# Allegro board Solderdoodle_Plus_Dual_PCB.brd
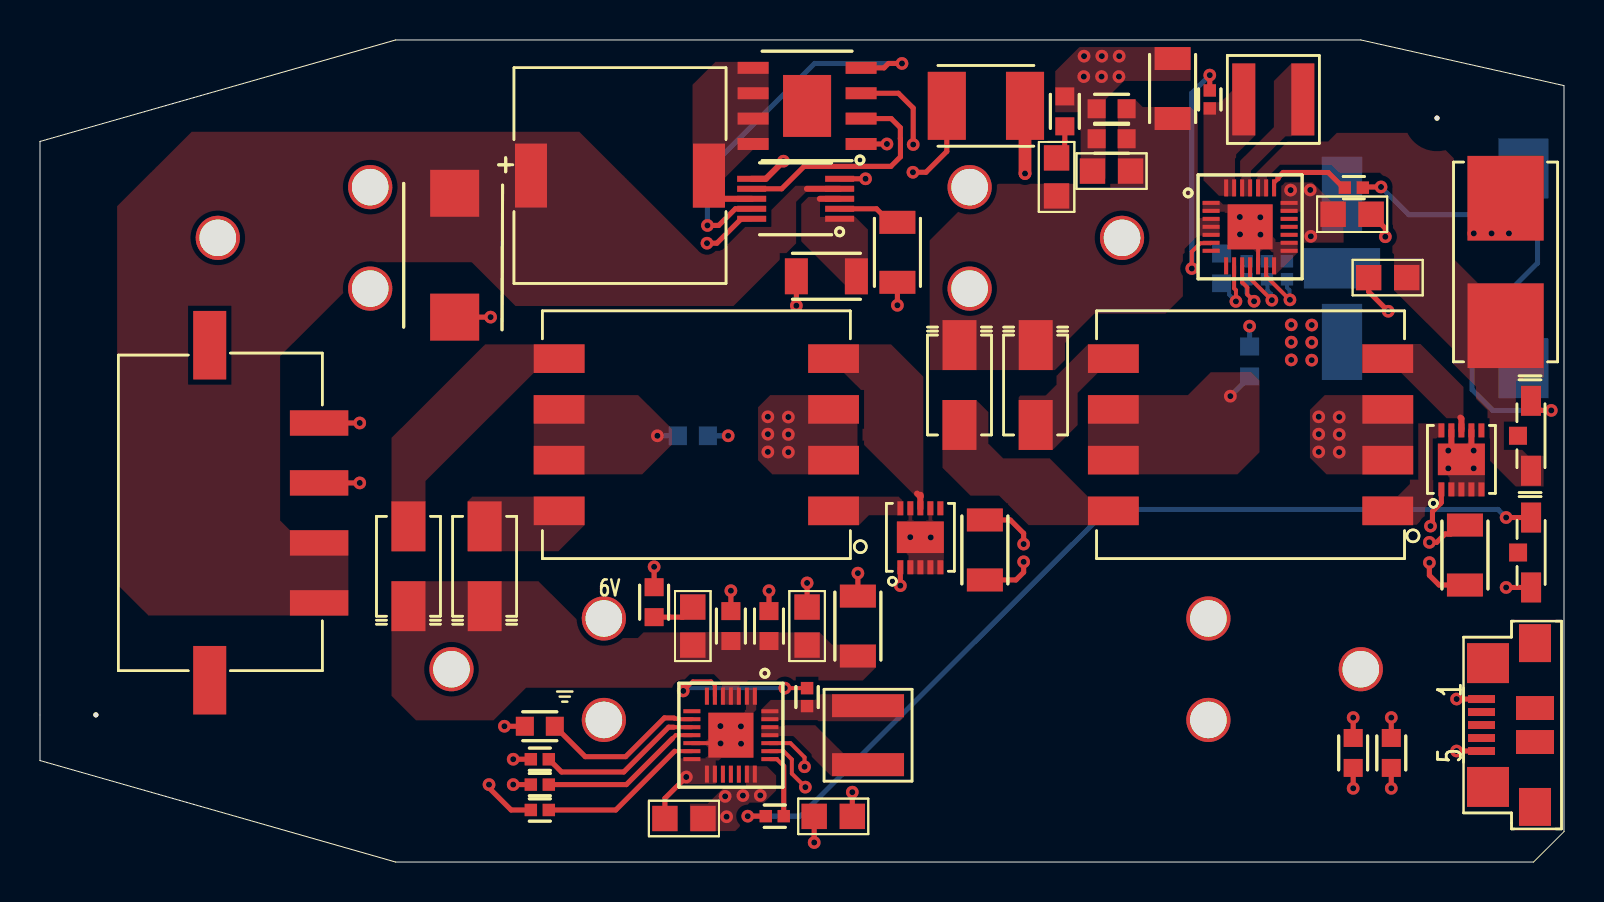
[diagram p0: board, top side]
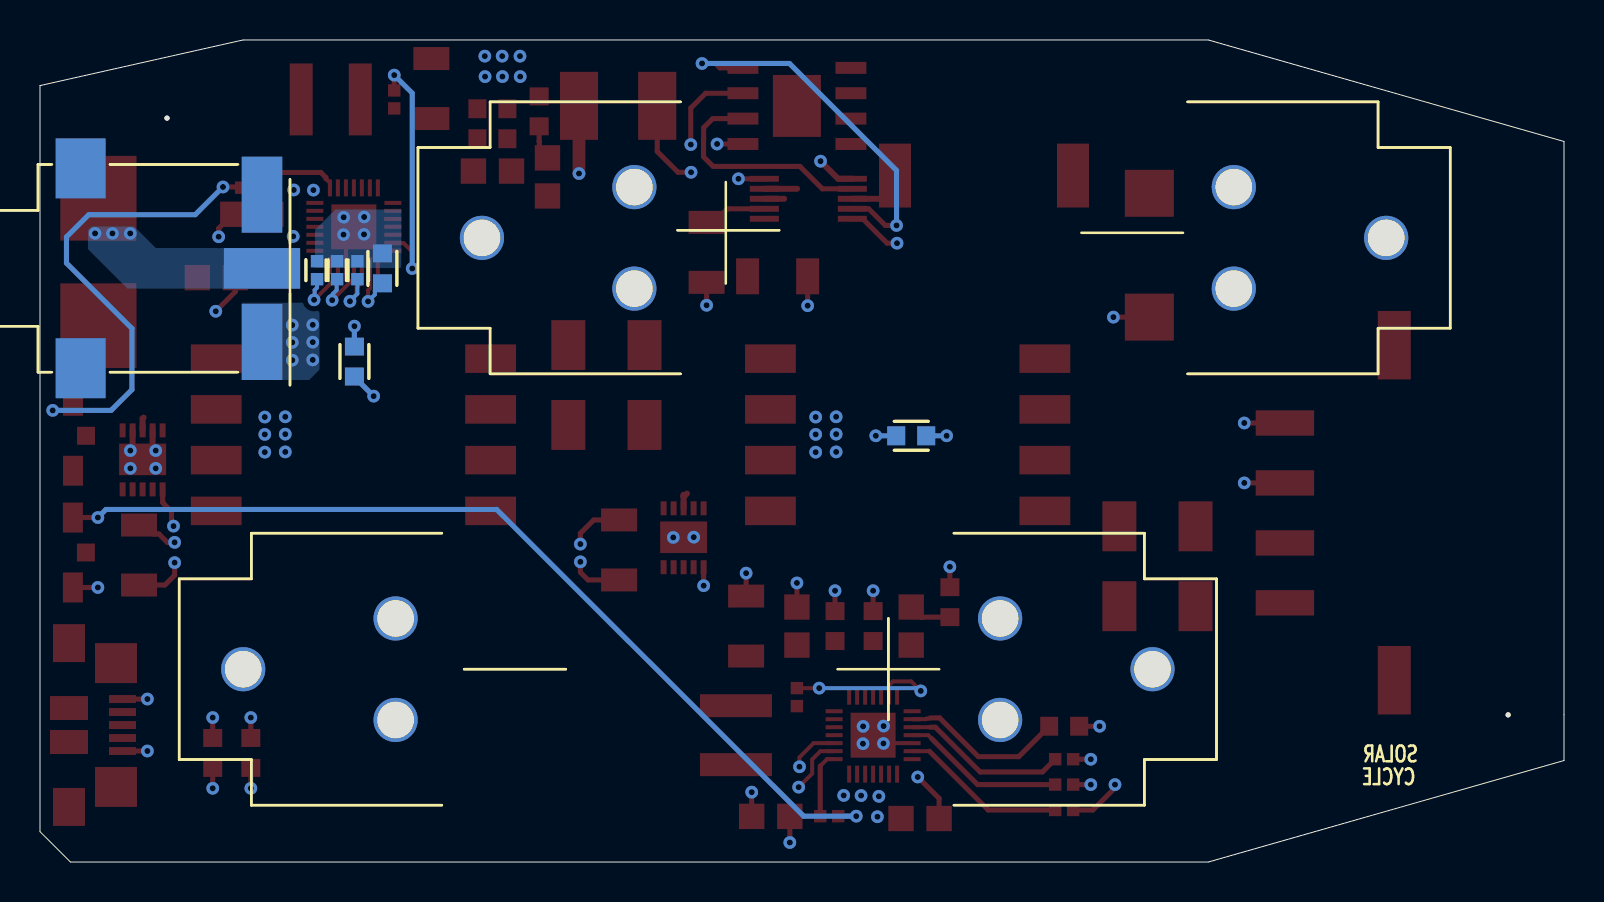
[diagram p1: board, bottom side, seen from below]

Outline 76.2 x 41.15 mm; copper layers: TOP, LAYER2_GND, LAYER3_PWR, BOTTOM. Coordinates in mm from the lower left corner of the outline.
Outline path: 0,36.07 17.78,41.15 66.04,41.15 76.2,38.86 76.2,1.52 74.68,0 17.78,0 0,5.08 0,36.07

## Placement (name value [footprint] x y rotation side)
BT1  -  [BAT_54]  46.48 31.24 0 bottom
BT2  -  [BAT_54]  28.19 9.65 180 bottom
BT3  -  [BAT_54]  16.51 31.24 180 bottom
BT4  -  [BAT_54]  58.42 9.65 0 bottom
C1  -  [C0805]  53.58 34.58 0 top
C2  -  [C0805]  38.35 11.81 270 top
C3  -  [C1206]  71.25 15.37 270 top
C4  -  [C0805]  67.38 29.25 180 top
C5  -  [C0402]  60.33 29.62 90 bottom
C6  -  [C0603]  59.08 29.72 90 bottom
C7  -  [C0402]  58.49 38.17 270 top
C8  -  [C0402]  38.35 8.25 270 top
C9  -  [C0603]  24.99 6.8 180 top
C10  -  [C0805]  50.83 34.29 270 top
C11  -  [C0805]  32.64 11.81 270 top
C12  -  [C0402]  24.99 5.15 180 top
C13  -  [C0805]  32.2 2.18 180 top
C14  -  [C0805]  39.66 2.29 0 top
C15  -  [C0603]  53.58 37.7 0 top
C16  -  [C1206]  56.63 38.72 90 top
C17  -  [C1206]  47.24 15.62 90 top
C18  -  [C0603]  34.54 11.81 270 top
C19  -  [C1206]  40.89 11.81 90 top
C20  -  [C0603]  65.66 5.46 270 top
C21  -  [C1206]  42.87 30.52 270 top
C22  -  [C1206]  39.32 29.32 180 top
C23  VAL*  [C1812]  47.29 37.85 0 top
C24  -  [C2917]  20.73 30.37 270 top
C25  -  [C0603]  67.56 5.46 270 top
C26  -  [C0805]  65.61 32.42 0 top
D1  -  [SMA]  49.78 23.88 90 top
D2  -  [SMA]  18.42 14.81 270 top
D3  -  [SMA]  45.97 23.88 90 top
D4  -  [SMA]  22.23 14.81 270 top
F1  -  [FUSE_SM]  73.28 30.04 90 top
J1  -  [4PIN_CON]  15.42 17.48 270 top
L1  -  [IND_4X4]  61.66 38.17 0 top
L2  -  [IND_4X4]  41.4 6.35 270 top
L3  -  [IND_10X10]  29 34.36 180 top
LED2  -  [LED_C110]  74.55 21.34 90 top
LED4  -  [LED_C110]  74.55 15.49 90 top
NOREF  -  []  523.95 -242.34 0 top
NOREF#2  -  []  -314.25 -255.04 0 top
NOREF#3  -  []  35.48 -64.31 0 top
NOREF#4  -  [unnamed#2]  69.85 37.24 180 bottom
NOREF#5  -  [unnamed#2]  2.79 7.37 180 bottom
R1  -  [R0603]  60.48 25.05 90 bottom
R2  -  [R0603]  53.58 36.2 0 top
R3  -  [R0402]  36.74 2.3 0 top
R4  -  [R0603]  32.64 21.34 0 bottom
R6  -  [R0603]  36.45 11.81 270 top
R7  -  [R0402]  61.35 29.62 270 bottom
R8  -  [R0402]  24.99 3.88 0 top
R10  -  [R0402]  65.69 33.75 180 top
R11  -  [R0402]  62.35 29.62 270 bottom
R12  -  [R0402]  24.99 2.61 0 top
R15  -  [R0603]  51.24 37.57 270 top
R16  -  [R0603]  30.71 13.01 270 top
S1  -  [ESWITCH]  65.1 29.72 270 bottom
T1  -  [T240V]  60.53 21.39 90 top
T2  -  [T240V]  32.82 21.39 90 top
U1  -  [SOIC_10]  71.07 20.15 90 top
U2  -  [SOIC_10]  44.02 16.26 90 top
U3  -  [QFN_28]  60.51 31.79 0 top
U4  -  [QFN_28]  34.54 6.35 270 top
U5  -  [SOP_10]  37.78 33.2 180 top
U6  -  [SOIC_8]  38.35 37.85 180 top
USB  -  [USB_B]  72.08 6.86 90 top

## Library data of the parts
BT1-BT4 = 54
C1 C2 C10 C11 C13 C26 = C0805C225K8RACTU
C3 C16 C17 C19 = GRM31CR71E106K
C4 C14 = C2012X5R1C226K
C5 C7 C8 C12 = C1005X5R1E104K
C6 C9 = C1608X5R1C225K_0P80
C15 C18 C20 C25 = GRM188R71E105K
C21 = C3216JB2E104K160AA
C22 = C3216X7R1C105M
C23 = C4532X5R1E106M
C24 = 10TPB220M
D1-D4 = B230A-13-F
F1 = 0154005_DRT
J1 = 662104145021
L1 L2 = IFSC1515AHER4R7M01
L3 = CDRH104R-7R0NC
LED2 LED4 = HSMG-C110
R1 R4 = RCS06030000Z0EA
R2 R6 = CRCW06031K00JNEAHP
R3 R10 = CRCW04022K20FKED
R7 R8 = CRCW04023K00FKED
R11 R12 = CRCW04021K20FKED
R15 R16 = ERJ-3RQJR56V
S1 = 500ASSP1SM6QE
T1 T2 = TGM-H240V8LF
U1 U2 = MAX13253ATB
U3 U4 = MAX8903GETI
U5 = MAX1791EUB
U6 = FDS8958A
USB = ZX62R-B-5P

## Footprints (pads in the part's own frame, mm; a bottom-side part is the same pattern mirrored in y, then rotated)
4PIN_CON
  rect 1.27x2.921 smd: 1(-4.501,-1.46) 2(-1.501,-1.46) 3(1.501,-1.46) 4(4.501,-1.46)
  rect 3.429x1.651 smd: 5(-8.395,-6.929) 6(8.374,-6.929)
BAT_54
  round 2.21 hole 1.829: 1(0,2.54) 2(7.62,0) 3(0,-2.54)
C0402
  rect 0.62x0.62 smd: 1(-0.45,0) 2(0.45,0)
C0603
  rect 0.899x0.95 smd: 1(-0.749,0) 2(0.749,0)
C0805
  rect 1.27x1.27 smd: 1(-0.953,0) 2(0.953,0)
C1206
  rect 1.151x1.801 smd: 1(-1.501,0) 2(1.501,0)
C1812
  rect 1.905x3.404 smd: 1(-1.956,0) 2(1.956,0)
C2917
  rect 2.349x2.451 smd: 1(-3.099,0) 2(3.099,0)
ESWITCH
  rect 3x2.499 smd: (-5.001,-9.07) (5.001,-9.07)
  rect 3.81x2.029 smd: 1(-3.686,0) 3(3.686,0)
  rect 2.029x3.81 smd: 2(0,0)
FUSE_SM
  rect 4.239x3.81 smd: 1(-3.19,0) 2(3.19,0)
IND_4X4
  rect 1.151x3.599 smd: 1(-1.476,0) 2(1.476,0)
IND_10X10
  rect 1.6x3.2 smd: 1(-4.45,0) 2(4.45,0)
LED_C110
  rect 0.899x0.899 smd: (0,0.65)
  rect 1.501x1.001 smd: 1(1.75,0) 2(-1.75,0)
QFN_28
  rect 0.851x0.201 smd: 1(-1.951,1.199) 2(-1.951,0.8) 3(-1.951,0.399) 4(-1.951,0) 5(-1.951,-0.399) 6(-1.951,-0.8) 7(-1.951,-1.199) 15(1.951,-1.199) 16(1.951,-0.8) 17(1.951,-0.399) 18(1.951,0) 19(1.951,0.399) 20(1.951,0.8) 21(1.951,1.199)
  rect 0.201x0.851 smd: 8(-1.199,-1.951) 9(-0.8,-1.951) 10(-0.399,-1.951) 11(0,-1.951) 12(0.399,-1.951) 13(0.8,-1.951) 14(1.199,-1.951) 22(1.199,1.951) 23(0.8,1.951) 24(0.399,1.951) 25(0,1.951) 26(-0.399,1.951) 27(-0.8,1.951) 28(-1.199,1.951)
  rect 2.25x2.25 smd: 29(0,0)
R0402
  rect 0.62x0.62 smd: 1(-0.45,0) 2(0.45,0)
R0603
  rect 0.899x0.95 smd: 1(-0.749,0) 2(0.749,0)
SMA
  rect 2.499x1.699 smd: 1(-1.999,0) 2(1.999,0)
SOIC_8
  rect 2.4x3.099 smd: (0,0)
  rect 1.549x0.599 smd: 1(-2.7,1.905) 2(-2.7,0.635) 3(-2.7,-0.635) 4(-2.7,-1.905) 5(2.7,-1.905) 6(2.7,-0.635) 7(2.7,0.635) 8(2.7,1.905)
SOIC_10
  rect 0.701x0.3 smd: 1(-1.501,1.001) 2(-1.501,0.5) 3(-1.501,0) 4(-1.501,-0.5) 5(-1.501,-1.001) 6(1.45,-1.001) 7(1.45,-0.5) 8(1.45,0) 9(1.45,0.5) 10(1.45,1.001)
  rect 1.58x2.349 smd: 11(0,0)
SOP_10
  rect 1.45x0.3 smd: 1(-2.2,1.001) 2(-2.2,0.5) 3(-2.2,0) 4(-2.2,-0.5) 5(-2.2,-1.001) 6(2.2,-1.001) 7(2.2,-0.5) 8(2.2,0) 9(2.2,0.5) 10(2.2,1.001)
T240V
  rect 1.43x2.54 smd: 1(-3.81,-6.861) 2(-1.27,-6.861) 3(1.27,-6.861) 4(3.81,-6.861) 5(3.81,6.861) 6(1.27,6.861) 7(-1.27,6.861) 8(-3.81,6.861)
unnamed#2
  round 0.254 hole 2.794 unplated: (0,0)
USB_B
  rect 1.9x1.6 smd: (-4.1,-2.675) (4.1,-2.675)
  rect 1.999x2.101 smd: (-3.099,-0.325) (3.099,-0.325)
  rect 1.199x1.9 smd: (-0.851,-2.675) (0.851,-2.675)
  rect 0.399x1.349 smd: 1(1.3,0) 2(0.65,0) 3(0,0) 4(-0.65,0) 5(-1.3,0)

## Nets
GND: BT3.1 BT3.2 BT3.3 C1.1 C4.2 C5.2 C6.2 C14.1 C15.1 C16.2 C26.2 LED4.2 R1.2 R2.1 R7.1 R11.1 R15.1 U3.1 U3.2 U3.12 U3.14 U3.15 U3.16 U3.29 U4.23 U4.24
BATT1: BT1.1 BT1.2 BT1.3 C26.1 U3.20 U3.21
BATT2: BT2.1 BT2.2 BT2.3 C13.1 U4.20 U4.21
F1: C4.1 F1.1 LED2.2 U3.23 U3.24
GNF: C3.2 C17.2 C20.2 C25.2 U1.2 U1.3 U1.4 U1.5 U1.7 U1.9 U1.11 U2.2 U2.3 U2.4 U2.5 U2.7 U2.9 U2.11 USB.5
GNG: BT4.1 BT4.2 BT4.3 C2.1 C9.2 C12.2 C13.2 C14.2 C18.1 C19.2 C21.2 C22.2 C23.2 C24.2 J1.2 R4.2 R6.1 R8.1 R12.1 R16.1 U4.1 U4.2 U4.12 U4.14 U4.15 U4.16 U4.29 U5.6 U6.1
LED1: LED2.1 R10.1
LED2: LED4.1 R3.1
N0006: C10.1 R15.2
N0180: D1.1 T1.5
N0181: D3.1 T1.8
N0268: R1.1 T1.6 T1.7
N0367: C11.1 R16.2
N0372: D2.1 T2.5
N0373: D4.1 T2.8
N0374: C8.2 L2.1 U4.27 U4.28
N0375: L2.2 U4.25 U4.26
N0384: R4.1 T2.6 T2.7
S1: F1.2 S1.2
U1T1: T1.1 U1.10
U1T2: T1.4 U1.8
U2T1: T2.1 U2.10
U2T2: T2.4 U2.8
U3BST: C7.1 U3.6
U3CHG: R10.2 U3.22
U3CS: L1.2 U3.25 U3.26
U3CT: C5.1 U3.10
U3DC: C1.2 C10.2 C15.2 C16.1 D1.2 D3.2 R2.2 U3.3 U3.4 U3.5
U3IDC: R7.2 U3.11
U3ISET: R11.2 U3.13
U3LX: C7.2 L1.1 U3.27 U3.28
U3VL: C6.1 U3.9
U4BST: C8.1 U4.6
U4CHG: R3.2 U4.22
U4CT: C12.1 U4.10
U4DC: C2.2 C11.2 C18.2 C19.1 D2.2 D4.2 R6.2 U4.3 U4.4 U4.5
U4IDC: R8.2 U4.11
U4ISET: R12.2 U4.13
U4VL: C9.1 U4.9
U5CS: L3.1 U5.8 U6.5 U6.6 U6.7 U6.8
U5DH: U5.9 U6.4
U5DL: U5.7 U6.2
U5OUT: C24.1 J1.3 J1.4 L3.2 U5.4
U5REF: C21.1 U5.2
U5VL: C22.1 U5.1 U5.3
U5VP: C23.1 J1.1 S1.3 U5.5 U5.10 U6.3
USB: C3.1 C17.1 C20.1 C25.1 T1.2 T1.3 T2.2 T2.3 U1.1 U2.1 USB.1

Pads without a net: J1 5 6; S1 1; U1 6; U2 6; U3 7 8 17 18 19; U4 7 8 17 18 19; USB 2 3 4

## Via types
v1: diameter 0.635, hole 0.305, TOP to BOTTOM, 107 vias

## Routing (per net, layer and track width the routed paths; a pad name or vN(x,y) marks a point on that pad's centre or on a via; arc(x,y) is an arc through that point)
GND: length 30.1
  TOP w0.198: U3.12 60.9,31.39 U3.29 ; U4.23 37.18,5.55 37.59,5.14 37.59,4.42 v1(38.27,3.75) ; U4.24 37.52,5.95 38.23,5.24 v1(38.23,4.77)
  TOP w0.254: LED4.2 v1(73.31,13.74) ; C14.1 v1(38.71,0.98) ; v1(67.27,31.3) 67.27,31.72 C26.2 ; v1(67.41,27.57) 66.43,28.55 C4.2
  LAYER2_GND w0.635: BT3.2 9.89,30.25 ; BT3.2 9.89,32.24 ; BT3.2 7.89,30.25 ; BT3.2 7.89,32.24 ; BT3.3 17.51,29.7 ; BT3.3 15.51,27.71 ; BT3.3 15.51,29.7 ; BT3.1 17.51,34.78 ; BT3.1 17.51,32.79 ; BT3.1 15.51,32.79 ; BT3.1 15.51,34.78
  BOTTOM w0.254: R1.2 v1(60.48,26.82)
  vias: v1(52.2,40.34) v1(52.19,39.31) v1(53.09,40.34) v1(53.08,39.31) v1(53.96,40.34) v1(53.95,39.31) v1(59.99,32.29) v1(60,31.42) v1(61.02,32.27) v1(61.02,31.4)
BATT1: length 16.9
  LAYER3_PWR w0.635: BT1.2 55.1,30.25 ; BT1.2 53.11,32.24 ; BT1.2 53.11,30.25 ; BT1.2 55.1,32.24 ; 45.49,29.7 BT1.1 ; BT1.1 47.48,29.7 ; BT1.1 47.48,27.71 ; BT1.1 45.49,27.71 ; 45.49,32.79 BT1.3 ; BT1.3 45.49,34.78 ; BT1.3 47.48,34.78 ; BT1.3 47.48,32.79
  vias: v1(62.53,33.63) v1(63.51,33.64) v1(63.54,31.32)
BATT2: length 16.9
  LAYER3_PWR w0.635: 27.2,11.2 BT2.1 ; BT2.1 29.19,11.2 ; BT2.1 27.2,13.19 ; BT2.1 29.19,13.19 ; BT2.3 29.19,6.12 ; BT2.3 29.19,8.11 ; BT2.3 27.2,8.11 ; BT2.3 27.2,6.12 ; 19.58,8.66 BT2.2 ; BT2.2 21.57,8.66 ; BT2.2 21.57,10.65 ; BT2.2 19.58,10.65
  vias: v1(34.26,3.29) v1(34.33,2.27) v1(35.15,3.33) v1(36.01,3.34)
GNF: length 10.8
  TOP w0.254: v1(69.47,14.99) 69.47,14.35 69.95,13.87 C3.2 ; C17.2 48.51,17.12 49.18,16.45 v1(49.18,15.92) ; USB.5 v1(70.83,5.56) ; C25.2 v1(67.56,3.69) ; C20.2 v1(65.66,3.69)
  TOP w0.3: v1(71.68,20.59) 71.57,20.71 U1.7 ; v1(70.41,20.59) 70.57,20.75 U1.9
  vias: v1(43.51,16.26) v1(44.54,16.25) v1(70.41,19.71) v1(71.68,19.71)
GNG: length 47.8
  TOP w0.198: U4.29 34.15,5.95 U4.12
  TOP w0.254: C19.2 v1(40.89,14.46) ; R16.1 v1(30.71,14.78) ; R12.1 23.56,2.61 22.45,3.71 v1(22.45,3.88) ; C9.2 v1(23.22,6.8) ; R8.1 v1(23.66,3.88) ; C2.1 v1(38.35,13.97) ; C22.2 v1(37.82,27.85) ; U6.1 v1(42.35,35.94) ; v1(32.31,4.26) 31.24,3.19 C13.2 ; C21.2 v1(42.87,27.87) ; C14.2 v1(40.61,3.5) ; C18.1 v1(34.54,13.58) ; R6.1 v1(36.45,13.58) ; J1.2 v1(15.99,18.98) ; C12.2 v1(23.66,5.15) ; C24.2 v1(22.53,27.27)
  TOP w0.3: v1(37.17,35.08) 36.29,34.2 U5.6
  TOP w0.635: v1(49.25,34.46) C23.2
  LAYER2_GND w0.635: 57.42,11.2 BT4.3 ; BT4.3 57.42,13.19 ; BT4.3 59.42,11.2 ; BT4.3 59.42,13.19 ; 57.42,8.11 BT4.1 ; BT4.1 57.42,6.12 ; BT4.1 59.42,6.12 ; BT4.1 59.42,8.11 ; 65.04,8.66 BT4.2 ; BT4.2 65.04,10.65 ; BT4.2 67.04,8.66 ; BT4.2 67.04,10.65
  BOTTOM w0.254: R4.2 v1(34.41,21.34)
  vias: v1(34.02,6.8) v1(34.03,5.94) v1(35.04,6.79) v1(35.05,5.92)
LED1: length 24.4
  TOP w0.254: v1(75.56,22.61) 75.03,22.61 LED2.1 ; R10.1 66.18,33.79 v1(67.05,33.79)
  BOTTOM w0.254: v1(67.05,33.79) 68.44,32.4 73.76,32.4 74.88,31.29 74.88,29.98 71.6,26.71 71.6,23.65 72.64,22.61 v1(75.56,22.61)
LED2: length 46.6
  TOP w0.254: LED4.1 v1(73.31,17.24) ; R3.1 v1(35.39,2.3)
  BOTTOM w0.254: v1(35.39,2.3) 38.02,2.3 53.37,17.65 72.9,17.65 v1(73.31,17.24)
N0006: length 1.8
  TOP w0.254: R15.2 51.24,36.07 51.23,36.06 51.23,35.5 50.98,35.25 C10.1
N0268: length 1.4
  BOTTOM w0.254: R1.1 60.48,24.28 v1(59.52,23.32)
N0367: length 2.1
  TOP w0.254: R16.2 32.13,12.26 C11.1
N0384: length 1
  BOTTOM w0.254: R4.1 v1(30.87,21.34)
S1:
  vias: v1(71.69,31.47) v1(72.58,31.47) v1(73.45,31.47)
U1T2: length 0.7
  TOP w0.3: 71.02,22.25 71.07,22.2 71.07,21.58
U2T2: length 0.9
  TOP w0.3: 44.02,18.28 44.02,18.31 44.03,18.32 44.03,18.38 ; 44.02,18.28 43.85,18.44 ; 44.02,18.28 U2.8
U3BST: length 12.8
  TOP w0.198: U3.6 58.53,30.97 58.01,30.97 57.59,30.55 v1(57.59,29.71)
  TOP w0.254: C7.1 v1(58.49,39.39)
  BOTTOM w0.254: v1(58.49,39.39) 57.59,38.49 v1(57.59,29.71)
U3CHG: length 4.4
  TOP w0.198: U3.22 61.7,34 61.9,34.2
  TOP w0.254: R10.2 65.18,33.75 64.41,34.52 62.16,34.52 61.9,34.26 61.9,34.2
U3CT: length 3.3
  TOP w0.198: v1(60.7,28.07) 60.37,28.4 60.37,28.76 60.11,29.02 U3.10
  BOTTOM w0.198: C5.1 60.33,28.45 60.7,28.08 v1(60.7,28.07)
U3IDC: length 3.3
  TOP w0.198: v1(61.59,28.12) 60.51,29.21 U3.11
  BOTTOM w0.198: v1(61.59,28.12) 61.56,28.15 61.56,28.43 61.37,28.63 61.37,29.15 R7.2
U3ISET: length 3.3
  TOP w0.198: U3.13 61.31,29.32 62.49,28.14 v1(62.5,28.14)
  BOTTOM w0.198: R11.2 62.35,28.76 62.47,28.63 62.47,28.17 v1(62.5,28.14)
U3VL: length 3
  TOP w0.198: v1(59.8,28.06) 59.8,28.63 59.71,28.72 U3.9
  BOTTOM w0.198: v1(59.8,28.06) 59.46,28.4 59.46,28.59 C6.1
U4BST: length 8.7
  TOP w0.198: v1(37.24,8.7) C8.1 ; v1(32.16,8.56) 32.64,9.04 33.55,9.04 33.74,8.85 U4.6
  BOTTOM w0.198: v1(32.16,8.56) 32.3,8.7 v1(37.24,8.7)
U4CHG: length 3.3
  TOP w0.198: 37.19,4.81 36.84,5.15 U4.22
  TOP w0.254: R3.2 37.19,4.81
U4CT: length 8.3
  TOP w0.198: 31.69,6.75 U4.10
  TOP w0.254: 31.69,6.75 31.43,6.75 29.19,4.51 26.08,4.51 C12.1
U4IDC: length 8.2
  TOP w0.198: 31.62,6.18 31.79,6.35 U4.11
  TOP w0.254: 31.62,6.18 29.32,3.88 R8.2
U4ISET: length 8.4
  TOP w0.198: 31.73,5.55 U4.13
  TOP w0.254: R12.2 28.79,2.61 31.73,5.55
U4VL: length 8.3
  TOP w0.198: 31.69,7.21 31.73,7.18 31.87,7.18 31.9,7.15 U4.9
  TOP w0.254: 31.69,7.21 31.22,7.21 29.28,5.28 27.26,5.28 C9.1
U5CS: length 2.4
  TOP w0.198: 33.37,33.53 33.7,33.2
  TOP w0.3: 33.7,33.2 U5.8
U5DH: length 19.4
  TOP w0.254: U6.4 42.2,39.75 42.42,39.97 v1(43.1,39.97) ; U5.9 34.77,32.7 33.93,31.86 v1(33.37,31.86)
  BOTTOM w0.254: v1(43.1,39.97) 38.73,39.97 33.37,34.62 v1(33.37,31.86)
U5DL: length 11.7
  TOP w0.254: U6.2 42.56,37.21 43.02,36.76 43.02,36.21 43.02,36.2 43.02,35.3 42.54,34.82 38.21,34.82 37.08,33.7 U5.7
U5OUT: length 1.6
  TOP w0.3: U5.4 38.35,33.7
U5REF: length 3.2
  TOP w0.254: C21.1 42.5,32.02 41.82,32.7 U5.2
U5VL: length 1
  TOP w0.3: U5.3 38.99,33.2
U5VP: length 15.2
  TOP w0.254: v1(43.65,34.53) 44.3,34.53 45.34,35.57 C23.1 ; v1(43.66,35.91) 43.66,37.74 42.92,38.48 U6.3 ; U5.10 35.06,32.2 33.84,30.98 v1(33.35,30.98) ; U5.5 v1(41.28,34.2) ; J1.1 v1(15.99,21.98)
  vias: v1(62.56,26.89) v1(62.56,26.02) v1(62.56,25.13) v1(63.59,26.88) v1(63.59,26.01) v1(63.59,25.12)
USB: length 11
  TOP w0.254: C17.1 48.8,14.12 49.18,14.5 v1(49.18,15.03) ; USB.1 v1(70.83,8.16) ; U1.1 70.07,18 70.02,17.95 70.02,17.94 69.62,17.55 69.62,16.91 v1(69.52,16.81) ; v1(69.47,16) 69.83,16 70.25,16.42 70.55,16.42 70.99,16.87 C3.1 ; C20.1 v1(65.66,7.23) ; C25.1 v1(67.56,7.23) ; U2.1 v1(43.02,13.83)
  vias: v1(36.39,22.29) v1(36.39,21.42) v1(36.39,20.53) v1(37.42,22.27) v1(37.42,21.4) v1(37.42,20.52) v1(63.94,22.29) v1(63.94,21.42) v1(63.94,20.53) v1(64.96,22.27) v1(64.96,21.4) v1(64.96,20.52)

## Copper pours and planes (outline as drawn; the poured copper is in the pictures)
GND on TOP: 53.28,34.02 52.03,34.02 52.03,36.58 51.71,36.9 50.76,36.9 50.76,39.58 51.98,40.79 57.53,40.79 57.53,39.1 54.2,39.1 53.28,38.18
GND on TOP: 62.88,31.09 61.85,31.09 61.63,31.31 61.63,32.92 59.15,32.92 58.98,33.09 58.13,33.09 58.13,32.49 59.35,32.49 59.38,32.46 59.38,30.67 60.66,30.67 60.81,30.53 60.81,29.42 61,29.42 61,30.54 61.13,30.67 61.46,30.67 61.61,30.52 61.61,29.42 61.8,29.42 62.88,30.5
GND on BOTTOM: 58.13,29.73 62.45,29.73 62.45,31.64 61.43,32.66 58.16,32.66 58.13,32.63
GND on LAYER2_GND: 75.95,12.37 73.46,12.37 72.84,12.99 72.84,21.89 72.19,22.53 62.14,22.53 47.58,37.09 27.23,37.09 13.12,22.98 13.12,9.68 19.31,3.48 35.06,3.48 37.31,5.74 38.32,5.74 39.29,4.77 39.29,0.25 17.82,0.25 0.25,5.27 0.25,35.88 17.82,40.89 66.01,40.89 75.95,38.66
BATT1 on TOP: 65.18,31 63.22,31 63.05,31.17 63.05,31.89 62.45,32.49 62.03,32.49 62.03,34 62.05,34.02 63.61,34.02 64.58,33.06 65.18,33.06
BATT1 on LAYER3_PWR: 64.87,27.18 44.65,27.18 44.65,35.5 62.58,35.5 64.87,33.21
BATT2 on TOP: 36.32,4.82 35.25,4.82 35.25,4.78 33.38,2.92 32.49,2.92 32.49,1.55 34.76,1.55 35.14,1.93 35.14,2.63 35.48,2.97 36.2,2.97 36.81,3.58 36.81,4.34
BATT2 on LAYER3_PWR: 37.14,1.34 20.6,1.34 17.26,4.67 17.26,12.05 19.34,14.12 33.19,14.12 37.14,10.17
F1 on TOP: 75.18,18.8 73.79,18.8 72.38,20.21 72.38,22.61 71.8,23.19 71.8,23.79 70.62,24.97 70.62,25.7 67.7,28.62 67.7,30.42 67.62,30.5 67.62,33.88 67,34.5 61.62,34.5 61.4,34.29 61.4,33.32 60.81,33.32 60.81,34.5 62.37,36.07 64.41,36.07 64.84,36.5 69.42,36.5 70.69,35.23 70.69,30.18 72.3,28.57 72.3,28.48 72.3,28.47 75.18,28.47 75.18,24.23 74.21,24.23 74,24.02 74,20.74 74.4,20.34 75.18,20.34 75.18,20.33
GNF on TOP: 72.24,18.3 70.42,18.3 70.42,19.31 70.37,19.36 69.9,19.36 69.9,20.94 70.36,20.94 70.42,21 70.42,21.96 70.72,21.96 70.72,21.01 70.78,20.94 71.32,20.94 71.42,21.05 71.42,21.96 71.72,21.96 71.72,20.98 71.75,20.94 72.24,20.94
GNF on TOP: 45.17,14.4 43.37,14.4 43.37,15.42 43.32,15.47 42.84,15.47 42.84,17.05 43.31,17.05 43.37,17.1 43.37,18.06 43.67,18.06 43.67,17.11 43.73,17.05 44.27,17.05 44.37,17.15 44.37,18.06 44.67,18.06 44.67,17.08 44.7,17.05 45.19,17.05 45.19,15.13 45.17,15.11
GNF on LAYER2_GND: 72.15,22.27 73.45,20.98 73.45,12.37 75.95,12.37 75.95,1.63 74.57,0.25 42.53,0.25 42.53,16.84 42.86,17.16 49.21,17.16 50.08,16.3 50.08,11.61 56.48,5.21 66.46,5.21 68.75,7.5 68.75,11.86 66.06,14.55 66.06,19.29 69.04,22.27
GNG on TOP: 33.84,3.9 32.11,3.9 31.97,4.04 31.97,5.25 33.34,5.25 33.42,5.33 33.42,5.71 33.28,5.85 32.17,5.85 32.17,6.05 33.29,6.05 33.42,6.18 33.42,7.48 35.2,7.48 35.25,7.52 35.25,8.72 35.84,8.72 35.84,7.65 35.67,7.48 35.67,5.22 34.08,5.22 33.84,4.99
GNG on LAYER2_GND: 17.82,40.89 66.01,40.89 75.95,38.66 75.95,1.63 74.57,0.25 17.82,0.25 0.25,5.27 0.25,35.88
N0180 on TOP: 48.94,20.63 50.63,20.63 51.88,21.87 51.88,23.48 52.89,24.48 54.94,24.48 54.94,25.91 52.4,25.91 50.83,24.34 50.83,23.89 50.29,23.36 49.02,23.36 48.94,23.27
N0181 on TOP: 54.94,16.86 49.43,16.86 47.95,18.34 46.52,18.34 45.13,19.74 45.13,23.13 46.81,23.13 47.41,22.52 47.41,20.95 48.15,20.21 50.48,20.21 52.4,18.29 54.94,18.29
N0268 on TOP: 52.4,19.4 52.4,23.37 57.39,23.37 58.54,24.52 60.57,24.52 60.98,24.11 60.98,20.51 59.87,19.4
N0372 on TOP: 17.57,15.55 17.57,21.23 22.26,25.91 27.23,25.91 27.23,24.48 24.69,24.48 19.27,19.07 19.27,15.55
N0373 on TOP: 21.38,15.55 25.92,15.55 27.23,16.86 27.23,18.29 21.62,18.29 21.38,18.05
N0374 on TOP: 36.07,7.05 43,7.05 43.2,7.25 43.2,8.4 39.03,8.4 38.75,8.12 36.54,8.12 36.07,7.65
N0375 on TOP: 43.2,4.3 39.56,4.3 37.61,6.25 36.07,6.25 36.07,6.85 38.76,6.85 40.16,5.45 43.2,5.45
N0384 on TOP: 24.69,19.4 24.69,23.37 29.91,23.37 31.61,21.67 31.61,20.9 30.11,19.4
S1 on BOTTOM: 63.2,28.7 71.82,28.7 73.8,30.68 73.8,31.63 73.62,31.81 71.48,31.81 70.41,30.73 63.2,30.73
U1T1 on TOP: 70.17,21.25 69.87,21.25 69.72,21.1 69.72,17.76 68.84,16.88 66.12,16.88 66.12,18.31 67.88,18.31 68.49,18.92 68.49,21.58 68.86,21.96 70.17,21.96
U1T2 on TOP: 70.87,21.25 71.17,21.25 71.17,23.78 69.02,25.93 66.12,25.93 66.12,24.48 68.06,24.48 70.37,22.17 70.69,22.17 70.87,22
U2T1 on TOP: 43.17,17.36 41.44,17.36 40.95,16.86 38.41,16.86 38.41,18.29 42.93,18.29 43.17,18.06
U2T2 on TOP: 44.17,17.36 43.87,17.36 43.87,18.22 41.13,20.96 41.13,23.55 40.2,24.48 38.41,24.48 38.41,25.91 42.55,25.91 44.17,24.29
U3CS on TOP: 63.71,36.37 62.62,36.37 60.6,34.35 60.6,33.32 60.01,33.32 60.01,35.1 61.69,36.78 61.69,39.1 62.57,39.97 63.71,39.97
U3DC on TOP: 58.98,31.3 58.02,31.3 57.14,30.41 57.14,28.32 56.27,27.45 52.72,27.45 51.25,25.98 51.25,24.97 50.9,24.63 44.49,24.63 44.49,31.12 47.31,33.95 53.89,33.95 53.89,38.18 54.75,38.18 55.14,37.79 57.54,37.79 57.89,37.44 57.89,32.53 58.13,32.29 58.98,32.29
U3LX on TOP: 59.8,33.32 58.97,33.32 58.18,34.11 58.18,38.03 59.03,38.03 59.61,38.61 59.61,39.97 60.76,39.97 60.76,36.37 59.8,35.42
U4DC on TOP: 17.57,14.06 17.57,8.32 18.8,7.09 22.67,7.09 24.31,8.72 34.05,8.72 34.05,7.88 35.04,7.88 35.04,8.72 35.41,9.09 41.15,9.09 41.79,9.74 41.79,10.88 39.6,10.88 38.99,11.49 36.94,11.49 36.92,11.51 33.29,11.51 33.27,11.49 30.18,11.49 29.89,11.21 27.76,11.21 24.92,14.06
U5CS on TOP: 34.23,32.76 34.23,34.23 35.64,35.64 36.43,35.64 36.43,40.05 33.77,40.05 32.63,38.91 32.63,32.76
U5OUT on TOP: 15.42,12.34 5.42,12.34 3.86,13.91 3.86,32.82 7.58,36.55 26.97,36.55 32.89,30.63 34.1,30.63 35.27,31.8 35.73,31.8 37.78,33.85 40.71,33.85 40.71,33.55 39.26,33.55 38.37,32.66 38.37,31.53 34.67,27.83 23.77,27.83 21.58,30.02 16.7,30.02 12.01,25.33 12.01,17.1 12.49,16.61 15.42,16.61
U5VL on TOP: 41.39,28.42 40.25,28.42 40.25,28.88 38.06,31.07 38.06,32.93 38.48,33.35 40.71,33.35 40.71,33.05 39.26,33.05 39.12,32.91 39.12,32.42 39.19,32.35 40.71,32.35 41.39,31.66
U5VP on BOTTOM: 66.11,24.13 62.75,24.13 62.23,24.65 62.23,27.74 62.49,28 66.07,28 66.11,27.95
U5VP on LAYER3_PWR: 44.24,40.27 44.24,26.72 49.31,26.72 50.04,27.45 63.79,27.45 65.03,26.21 65.03,25 61.6,21.56 40.15,21.56 38.41,23.31 35.85,23.31 33.72,21.18 13.6,21.18 10.37,24.41 10.37,35.45 13.84,38.92 17.09,38.92 18.44,40.27
USB on TOP: 68.66,19.4 68.66,23.37 64.24,23.37 63.5,22.63 63.5,20.23 64.33,19.4
USB on TOP: 40.95,19.4 40.95,23.37 36.51,23.37 35.9,22.77 35.9,20.12 36.62,19.4
USB on LAYER3_PWR: 37.26,1.33 72.2,1.33 74.81,3.94 74.81,19.25 71.08,22.97 35.88,22.97 35.45,22.54 35.45,3.14

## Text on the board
BOTTOM: SOLDER SIDE ETCH | 4
Ref Des/Silkscreen Bottom: SOLAR | CYCLE | BOTTOM SILKSCREEN | 4
User.Comments: SOLARCYCLE
Ref Des/Silkscreen Top: 6V | TOP SILKSCREEN | 5
LAYER2_GND: LAYER 2 GND PLANE | 2
LAYER3_PWR: LAYER 3 PWR PLANE | 3
PAGE_OUTLINE: (408) 582-2787  johnc@cdspcb.com | CORCORAN DESIGN SERVICE,INC | SOLARCYCLE
PASTEMASK_BOTTOM: PASTEMASK BOTTOM | 10
User.11: NOTES (UNLESS OTHERWISE SPECIFIED): | SOLDERED ENTITY. | 4.   SOLDER MASK BOTH SIDES WITH LIQUID PHOTO IMAGEABLE SOLDER MASK (LPI), GREEN. | 5.   SILKSCREEN TOP SIDE WITH WHITE EPOXY NON CONDUCTIVE INK.  SILKSCREEN MAY BE TRIMMED OFF ANY | 2.   NUMBER OF LAYERS: 4 | 3.   FINISH: HOT AIR SOLDER LEVELED (HASL) | 1.   MATERIAL : FR-4 | NOTE: NOMINAL THICKNESS = 40 MILS (+/-10%) | STACKUP | DETAIL `A'
User.12: LED2 | LED4 | NOTES (UNLESS OTHERWISE SPECIFIED): | 1.  Workmanship standards and acceptability criteria shall meet | IPC-A-610 (latest revision). | J1 | D2 | D4 | C13 | T2 | C14 | U2 | D3 | C10 | D1 | C1 | T1 | C26 | C4 | U1 | F1 | S1 | 10/1 | R12 | C12 | C9 | R8 | L3 | U4 | C22 | R3 | U5 | U6 | L2 | C23 | C17 | R15 | C15 | R2 | C16 | U3 | L1 | R10 | BT4 | R1 | BT1 | R4 | BT2 | BT3 | C11 | C2 | 1 | 5 | C24 | R16 | C8 | C21 | C18 | R6 | C19 | C7 | C20 | C25 | C3 | USB | R11 | R7 | C5 | C6 | TOP SIDE | BOTTOM  SIDE
User.14: SILKSCREEN TOP | SOLDER MASK TOP | LAYER 1  - TOP ETCH  - 2  OZ. | LAYER 2  - GND PLANE - 2  OZ. | LAYER 3  - PWR PLANE - 2  OZ. | LAYER 4  - BOTTOM ETCH - 2  OZ. | SOLDERMASK BOTTOM | SILKSCREEN BOTTOM | PREPREG | CORE | .040"+/-.10% | (NOM)
User.16: FIGURE | SIZE | 12.0 | 72.0 | 110.0 | DRILL CHART: TOP to BOTTOM | ALL UNITS ARE IN MILS | TOLERANCE | +0.0/-12.0 | +3.0/-3.0 | PLATED | NON-PLATED | QTY | 107 | 12 | 2
